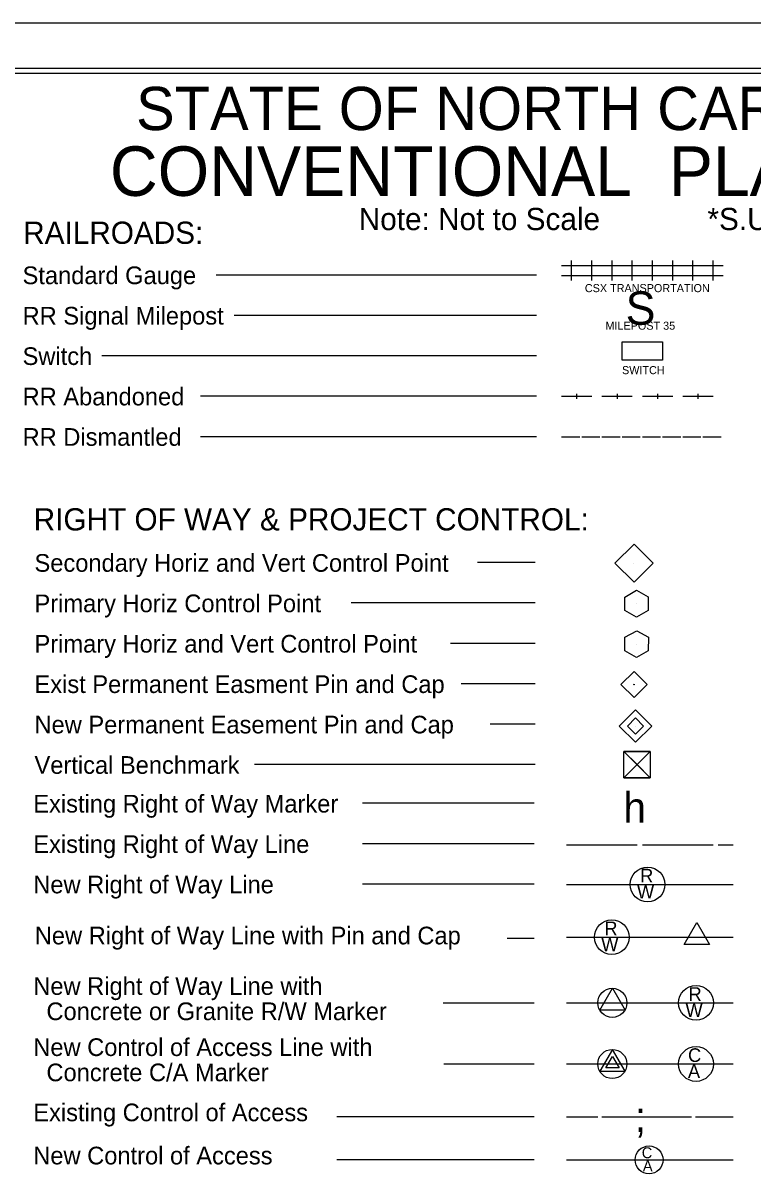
# Model space of a CAD drawing. Extents: x 1578579.3 to 1578613, y 915799 to 915821.
# Drawn here: x 1578590.52 to 1578597.74, y 915809.56 to 915820.96 of the extents above; entities that cross this region are included whole.
import ezdxf

# ---------------------------------------------------------------- set-up
doc = ezdxf.new("R2010")
doc.units = 0
for name, color, linetype in [('Default', 7, 'Continuous'), ('Prop ROW Permanent Easement CELL', 7, 'Continuous'), ('Sheet Cutting Line CELL', 7, 'Continuous'), ('Sheet Plot Border Inside CELL', 7, 'Continuous'), ('Sheet Plot Border Outside CELL', 7, 'Continuous'), ('Sheet Symbology CELL', 7, 'Continuous')]:
    doc.layers.add(name, color=color, linetype=linetype)

msp = doc.modelspace()

# ---------------------------------------------------------------- linework, layer by layer
at = {"layer": 'Default'}
for p, q in [((1578596.567, 915815.616), (1578596.567, 915815.616)), ((1578596.593, 915815.216), (1578596.593, 915815.216)), ((1578596.593, 915814.816), (1578596.593, 915814.816)), ((1578596.568, 915814.415), (1578596.568, 915814.415)), ((1578596.598, 915813.623), (1578596.598, 915813.623))]:
    msp.add_line(p, q, dxfattribs=at)
for points in [[(1578596.379, 915815.616), (1578596.568, 915815.805), (1578596.757, 915815.616), (1578596.568, 915815.427)], [(1578596.476, 915814.883), (1578596.594, 915814.948), (1578596.711, 915814.884), (1578596.709, 915814.75), (1578596.592, 915814.681), (1578596.476, 915814.747)], [(1578596.438, 915814.415), (1578596.568, 915814.545), (1578596.697, 915814.415), (1578596.568, 915814.285)], [(1578596.468, 915813.753), (1578596.727, 915813.753), (1578596.727, 915813.493), (1578596.468, 915813.493)]]:
    msp.add_lwpolyline(points, close=True, dxfattribs=at)
for points in [[(1578596.593, 915815.083), (1578596.477, 915815.148), (1578596.477, 915815.281), (1578596.593, 915815.349), (1578596.709, 915815.283), (1578596.709, 915815.148), (1578596.593, 915815.083)], [(1578596.727, 915813.753), (1578596.468, 915813.493), (1578596.598, 915813.623), (1578596.727, 915813.493), (1578596.468, 915813.753)], [(1578596.598, 915813.623), (1578596.727, 915813.753), (1578596.468, 915813.753), (1578596.598, 915813.623)], [(1578596.598, 915813.623), (1578596.468, 915813.493), (1578596.727, 915813.493), (1578596.598, 915813.623)]]:
    msp.add_lwpolyline(points, dxfattribs=at)
msp.add_circle((1578596.568, 915814.415), 0.00253, dxfattribs=at)
at = {"layer": 'Prop ROW Permanent Easement CELL'}
msp.add_line((1578596.583, 915814.004), (1578596.583, 915814.004), dxfattribs=at)
for points in [[(1578596.583, 915814.165), (1578596.744, 915814.004), (1578596.583, 915813.843), (1578596.422, 915814.004)], [(1578596.583, 915814.084), (1578596.663, 915814.004), (1578596.583, 915813.923), (1578596.502, 915814.004)]]:
    msp.add_lwpolyline(points, close=True, dxfattribs=at)
at = {"layer": 'Sheet Cutting Line CELL'}
msp.add_line((1578612.97, 915820.963), (1578579.29, 915820.963), dxfattribs=at)
at = {"layer": 'Sheet Plot Border Inside CELL'}
msp.add_lwpolyline([(1578579.55, 915799.412), (1578612.88, 915799.412), (1578612.88, 915820.514), (1578579.55, 915820.514)], close=True, dxfattribs=at)
at = {"layer": 'Sheet Plot Border Outside CELL'}
msp.add_lwpolyline([(1578579.29, 915798.963), (1578612.97, 915798.963), (1578612.97, 915820.963), (1578579.29, 915820.963)], close=True, dxfattribs=at)
at = {"layer": 'Sheet Symbology CELL'}
for p, q in [((1578595.85, 915818.563), (1578596.05, 915818.563)), ((1578595.95, 915818.413), (1578595.95, 915818.613)), ((1578596.05, 915818.563), (1578596.25, 915818.563)), ((1578596.15, 915818.413), (1578596.15, 915818.613)), ((1578596.25, 915818.563), (1578596.45, 915818.563)), ((1578596.35, 915818.413), (1578596.35, 915818.613)), ((1578596.45, 915818.563), (1578596.65, 915818.563)), ((1578596.55, 915818.413), (1578596.55, 915818.613)), ((1578596.65, 915818.563), (1578596.85, 915818.563)), ((1578596.75, 915818.413), (1578596.75, 915818.613)), ((1578596.85, 915818.563), (1578597.05, 915818.563)), ((1578596.95, 915818.413), (1578596.95, 915818.613)), ((1578597.05, 915818.563), (1578597.25, 915818.563)), ((1578597.15, 915818.413), (1578597.15, 915818.613)), ((1578597.25, 915818.563), (1578597.45, 915818.563)), ((1578597.35, 915818.413), (1578597.35, 915818.613)), ((1578595.602, 915818.468), (1578592.433, 915818.468)), ((1578595.85, 915818.463), (1578596.05, 915818.463)), ((1578596.05, 915818.463), (1578596.25, 915818.463)), ((1578596.25, 915818.463), (1578596.45, 915818.463)), ((1578596.45, 915818.463), (1578596.65, 915818.463)), ((1578596.65, 915818.463), (1578596.85, 915818.463)), ((1578596.85, 915818.463), (1578597.05, 915818.463)), ((1578597.05, 915818.463), (1578597.25, 915818.463)), ((1578597.25, 915818.463), (1578597.45, 915818.463)), ((1578595.602, 915818.068), (1578592.611, 915818.068)), ((1578595.602, 915817.668), (1578591.303, 915817.668)), ((1578595.602, 915817.268), (1578592.278, 915817.268)), ((1578595.85, 915817.268), (1578596.15, 915817.268)), ((1578596, 915817.293), (1578596, 915817.243)), ((1578596.25, 915817.268), (1578596.55, 915817.268)), ((1578596.4, 915817.293), (1578596.4, 915817.243)), ((1578596.65, 915817.268), (1578596.95, 915817.268)), ((1578596.8, 915817.293), (1578596.8, 915817.243)), ((1578597.05, 915817.268), (1578597.35, 915817.268)), ((1578597.2, 915817.293), (1578597.2, 915817.243)), ((1578595.602, 915816.868), (1578592.278, 915816.868)), ((1578595.602, 915816.868), (1578592.278, 915816.868)), ((1578595.85, 915816.868), (1578596.03, 915816.868)), ((1578596.05, 915816.868), (1578596.23, 915816.868)), ((1578596.25, 915816.868), (1578596.43, 915816.868)), ((1578596.45, 915816.868), (1578596.63, 915816.868)), ((1578596.65, 915816.868), (1578596.83, 915816.868)), ((1578596.85, 915816.868), (1578597.03, 915816.868)), ((1578597.05, 915816.868), (1578597.23, 915816.868)), ((1578597.25, 915816.868), (1578597.43, 915816.868)), ((1578595.591, 915815.622), (1578595.02, 915815.622)), ((1578595.591, 915815.222), (1578593.77, 915815.222)), ((1578595.591, 915814.822), (1578594.752, 915814.822)), ((1578595.591, 915814.422), (1578594.857, 915814.422)), ((1578595.591, 915814.022), (1578595.144, 915814.022)), ((1578595.591, 915813.622), (1578592.814, 915813.622)), ((1578595.579, 915813.239), (1578593.88, 915813.239)), ((1578595.579, 915812.839), (1578593.88, 915812.839)), ((1578595.9, 915812.827), (1578596.6, 915812.827)), ((1578596.65, 915812.827), (1578597.35, 915812.827)), ((1578597.4, 915812.827), (1578597.55, 915812.827)), ((1578595.579, 915812.439), (1578593.88, 915812.439)), ((1578595.9, 915812.436), (1578597.55, 915812.436)), ((1578595.9, 915811.914), (1578597.55, 915811.914)), ((1578597.189, 915811.914), (1578597.189, 915811.914)), ((1578595.579, 915811.902), (1578595.314, 915811.902)), ((1578595.579, 915811.261), (1578594.679, 915811.261)), ((1578595.9, 915811.264), (1578597.55, 915811.264)), ((1578596.354, 915811.264), (1578596.354, 915811.264)), ((1578595.579, 915810.656), (1578594.687, 915810.656)), ((1578595.9, 915810.659), (1578597.55, 915810.659)), ((1578596.354, 915810.659), (1578596.354, 915810.659)), ((1578595.579, 915810.137), (1578593.628, 915810.137)), ((1578595.9, 915810.137), (1578596.209, 915810.137)), ((1578596.249, 915810.137), (1578597.137, 915810.137)), ((1578597.177, 915810.137), (1578597.55, 915810.137)), ((1578595.579, 915809.71), (1578593.628, 915809.71)), ((1578595.9, 915809.71), (1578597.55, 915809.71))]:
    msp.add_line(p, q, dxfattribs=at)
for points in [[(1578612.63, 915820.463), (1578582.63, 915820.463), (1578582.63, 915799.483), (1578612.63, 915799.483)], [(1578596.45, 915817.807), (1578596.85, 915817.807), (1578596.85, 915817.625), (1578596.45, 915817.625)], [(1578597.064, 915811.842), (1578597.189, 915812.058), (1578597.314, 915811.842)], [(1578596.229, 915811.192), (1578596.354, 915811.408), (1578596.479, 915811.192)], [(1578596.229, 915810.587), (1578596.479, 915810.587), (1578596.354, 915810.803)], [(1578596.288, 915810.621), (1578596.354, 915810.734), (1578596.419, 915810.621)]]:
    msp.add_lwpolyline(points, close=True, dxfattribs=at)
for centre, radius in [((1578596.702, 915812.436), 0.172), ((1578596.348, 915811.914), 0.172), ((1578596.353, 915811.264), 0.144), ((1578597.181, 915811.264), 0.172), ((1578596.353, 915810.659), 0.144), ((1578597.181, 915810.659), 0.172), ((1578596.717, 915809.71), 0.138)]:
    msp.add_circle(centre, radius, dxfattribs=at)

# ---------------------------------------------------------------- texts
for s, height, p in [('STATE OF NORTH CAROLINA, DIVISION OF HIGHWAYS', 0.42838, (1578591.641, 915819.903)), ('CONVENTIONAL  PLAN SHEET SYMBOLS', 0.48961, (1578591.382, 915819.252)), ('RAILROADS:', 0.22, (1578590.524, 915818.777)), ('Standard Gauge', 0.175, (1578590.518, 915818.378)), ('S', 0.33, (1578596.485, 915817.976)), ('RR Signal Milepost', 0.175, (1578590.518, 915817.978)), ('Switch', 0.175, (1578590.518, 915817.578)), ('RR Abandoned', 0.175, (1578590.518, 915817.178)), ('RR Dismantled', 0.175, (1578590.518, 915816.778)), ('RIGHT OF WAY & PROJECT CONTROL:', 0.22, (1578590.628, 915815.94)), ('Secondary Horiz and Vert Control Point', 0.175, (1578590.636, 915815.531)), ('Primary Horiz Control Point', 0.175, (1578590.636, 915815.131)), ('Primary Horiz and Vert Control Point', 0.175, (1578590.636, 915814.731)), ('Exist Permanent Easment Pin and Cap', 0.175, (1578590.636, 915814.331)), ('New Permanent Easement Pin and Cap', 0.175, (1578590.636, 915813.931)), ('Vertical Benchmark', 0.175, (1578590.636, 915813.531)), ('Existing Right of Way Marker', 0.175, (1578590.624, 915813.148)), ('h', 0.3, (1578596.463, 915813.047)), ('Existing Right of Way Line', 0.175, (1578590.624, 915812.748)), ('R', 0.135, (1578596.628, 915812.456)), ('New Right of Way Line', 0.175, (1578590.624, 915812.348)), ('W', 0.135, (1578596.597, 915812.297)), ('New Right of Way Line with Pin and Cap', 0.175, (1578590.639, 915811.843)), ('R', 0.135, (1578596.274, 915811.934)), ('W', 0.135, (1578596.243, 915811.775)), ('New Right of Way Line with', 0.175, (1578590.624, 915811.343)), ('R', 0.135, (1578597.107, 915811.284)), ('  Concrete or Granite R/W Marker', 0.175, (1578590.624, 915811.093)), ('W', 0.135, (1578597.077, 915811.125)), ('New Control of Access Line with', 0.175, (1578590.624, 915810.738)), ('C', 0.135, (1578597.102, 915810.679)), ('  Concrete C/A Marker', 0.175, (1578590.624, 915810.488)), ('A', 0.135, (1578597.101, 915810.52)), ('Existing Control of Access', 0.175, (1578590.624, 915810.092)), (';', 0.3, (1578596.575, 915809.987)), ('New Control of Access', 0.175, (1578590.624, 915809.665)), ('C', 0.108, (1578596.644, 915809.726)), ('A', 0.108, (1578596.655, 915809.597))]:
    msp.add_text(s, height=height, dxfattribs=at).set_placement(p)
for s, height, p in [('Note: Not to Scale', 0.22, (1578593.844, 915818.913)), ('*S.U.E. = Subsurface Utility Engineering', 0.22, (1578597.294, 915818.913)), ('CSX TRANSPORTATION', 0.08, (1578596.081, 915818.299)), ('MILEPOST 35', 0.08, (1578596.285, 915817.927)), ('SWITCH', 0.08, (1578596.449, 915817.487))]:
    msp.add_text(s, height=height, rotation=360, dxfattribs=at).set_placement(p)

doc.saveas('drawing.dxf')
